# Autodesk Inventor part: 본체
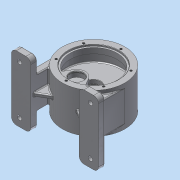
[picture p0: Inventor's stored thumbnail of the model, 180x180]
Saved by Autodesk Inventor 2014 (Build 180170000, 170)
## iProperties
Created: 2025-12
Part Number: 본체
Material: 알루미늄 6061
Document SubType Name: Modeling
Designer: dg
Density: 2.71 g/cm^3
Appearance: 알루미늄 - 평지
Mass: 5646.09 g
Surface Area: 3060.39 cm^2
Volume: 2083.43 cm^3
Author: dg
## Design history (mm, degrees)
sketch "스케치1"
  geometry: C1 r 97 at (0, 0); 1 further point
  constraints: 1 centre point, 1 coincident
  dimensions: "d0" = 194 diameter of C1
extrude "돌출1" new body sketch "스케치1" stored distance "d1" = 124; taper "d2" = 0 deg
sketch "스케치2"
  geometry: L1 (97, 62)-(-97, 62) reference; L2 (-97, -62)-(97, -62) reference; L3 (0, 62)-(0, -62); L4 (0, 62)-(78, 62); L5 (78, 62)-(78, 57); L6 (78, 57)-(73, 57); L7 (73, 57)-(73, 40); L8 (73, 40)-(87, 40); L9 (87, 40)-(87, 8); L10 (87, 8)-(21, 8); L11 (21, 8)-(21, -4); L12 (21, -4)-(19, -4); L13 (19, -4)-(19, -8); L14 (19, -8)-(87, -8); L15 (87, -8)-(87, -40); L16 (87, -40)-(73, -40); L17 (73, -40)-(73, -57); L18 (73, -57)-(78, -57); L19 (78, -57)-(78, -62); L20 (78, -62)-(0, -62); 1 further point
  constraints: 36 end point, 12 parallel, 4 perpendicular, 3 collinear, 3 vertical alignment, 2 midpoint, 2 point on line
  dimensions: "d3" = 156 diameter of L5 L3; "d4" = 146 diameter of L7 L3; "d5" = 174 diameter of L9 L3; "d6" = 5 distance of L4.end L5.end; "d8" = 32 distance of L8.end L9.end; "d9" = 22 distance between parallel lines of L8 L1; "d10" = 66 distance between parallel lines of L12 L1; "d11" = 42 diameter of L11 L3; "d12" = 38 diameter of L13 L3
revolve "회전1" sketch "스케치2" stored, may be unused: angle "d13" = 90 deg
sketch "스케치3"
  geometry: L1 (-23.383, -39)-(-37.148, -62.842); L2 (23.383, -39)-(37.148, -62.842); L3 (0, -52.5)-(0, -73); C1 r 78 at (0, 0) reference; A1 r 73 centre (0, 0) between (-37.148, -62.842) and (37.148, -62.842) reference; A2 r 27 centre (0, -52.5) between (23.383, -39) and (-23.383, -39)
  constraints: 6 end point, 5 point on circle, 2 tangent, 1 centre point, 1 vertical, 1 vertical alignment
  dimensions: "d14" = 52.5 distance of L3.start C1.centre; "d15" = 27 radius of A2; "d16" = 30 deg angle of L3 L2; "d17" = 30 deg angle of L3 L1
extrude "돌출2" join sketch "스케치3" distance "d18" = 17; taper "d19" = 0 deg
sketch "스케치4"
  geometry: L1 (-25.5, 57)-(-39, 57) reference; L2 (-39, 57)-(-62.842, 57) reference; L3 (78, 57)-(-78, 57) reference; L4 (87, -8)-(-87, -8) reference; L5 (-52.5, 57)-(-52.5, -8); L6 (-52.5, -8)-(-33.5, -8); L7 (-33.5, -8)-(-33.5, -4); L8 (-33.5, -4)-(-31.5, -4); L9 (87, 8)-(-87, 8) reference; L10 (-31.5, -4)-(-31.5, 8); L11 (-31.5, 8)-(-52.5, 8); L12 (-78, 62)-(78, 62) reference; L13 (-52.5, 57)-(-31.5, 57); L14 (-31.5, 57)-(-31.5, 53.95); L15 (-31.5, 53.95)-(-30.25, 53.95); L16 (-30.25, 53.95)-(-30.25, 52); L17 (-30.25, 52)-(-31.5, 52); L18 (-39, 40)-(-25.5, 40) reference; L19 (-62.842, 40)-(-39, 40) reference; L20 (-31.5, 52)-(-31.5, 40); L21 (-31.5, 40)-(-52.5, 40); 1 further point
  constraints: 26 end point, 10 point on line, 7 perpendicular, 2 parallel
  dimensions: "d20" = 52.5 distance from line of L5 point (0, 0); "d21" = 38 diameter of L7 L5; "d22" = 42 diameter of L10 L5; "d23" = 66 distance between parallel lines of L8 L12; "d24" = 42 diameter of L14 L5; "d25" = 44.5 diameter of L16 L5; "d26" = 1.95 distance of L15.end L16.end; "d27" = 12 distance of L17.end L20.end; "d28" = 42 diameter of L20 L5
revolve "회전2" sketch "스케치4" stored, may be unused: angle "d29" = 90 deg
sketch "스케치5"
  geometry: C1 r 78 at (0, 0) reference; 1 further point
  constraints: 1 vertical alignment
  dimensions: "d30" = 85 distance of C1.centre point (0, 85)
hole "구멍1" sketch "스케치5" at (0, 85) diameter "d31" = 6.917; stored, may be unused: countersink angle "d35" = 90 deg, drill point angle "d37" = 118 deg; dims "d32" = 16, "d33" = 4, "d34" = 2, "d36" = 18
node "작업 평면1"
sketch "스케치6"
  geometry: L1 (-97, -62)-(-97, 62) reference; L2 (97, -62)-(97, 62) reference; L3 (-75, 100)-(-135, 100); L4 (-135, 100)-(-135, -100); L5 (-135, -100)-(-75, -100); L6 (-75, -100)-(-75, 100); L7 (135, 100)-(75, 100); L8 (75, 100)-(75, -100); L9 (75, -100)-(135, -100); L10 (135, -100)-(135, 100); 3 further points
  constraints: 16 end point, 4 parallel, 2 equal length, 2 horizontal, 2 horizontal alignment, 2 midpoint, 2 perpendicular
  dimensions: "d42" = 150 distance between parallel lines of L8 L6; "d43" = 75 distance from line of point (0, 0) L6; "d44" = 60 distance of L3.start L3.end; "d45" = 200 distance of L3.end L4.end
extrude "돌출3" join sketch "스케치6" distance "d46" = 20; taper "d47" = 0 deg
fillet "모깎기1" dims "d48" = 15
sketch "스케치7"
  geometry: 3 further points
  constraints: 1 vertical alignment
  dimensions: "d49" = 150 distance of point (110, -75) point (110, 75); "d50" = 75 vertical distance of point (0, 0) point (110, 75); "d51" = 110 horizontal distance of point (110, 75) point (0, 0)
hole "구멍2" sketch "스케치7" at (110, -75), (110, 75) diameter "d52" = 13.5; stored, may be unused: countersink angle "d56" = 90 deg, drill point angle "d58" = 118 deg; dims "d53" = 16, "d54" = 33, "d55" = 2, "d57" = 18
sketch "스케치8"
  geometry: L1 (75, 85)-(75, -85) reference; L2 (75, 50)-(97, 50); L3 (97, 50)-(97, -50); L4 (97, -50)-(75, -50); L5 (75, -50)-(75, 50); 2 further points
  constraints: 8 end point, 2 parallel, 1 horizontal, 1 horizontal alignment, 1 midpoint, 1 perpendicular, 1 point on line
  dimensions: "d59" = 22 distance of L2.start L2.end; "d60" = 100 distance of L2.end L3.end
extrude "돌출4" join sketch "스케치8" stored distance "d61" = 20; taper "d62" = 0 deg
sketch "스케치9"
  geometry: L1 (75, -100)-(75, -61.514) reference; L2 (75, -120)-(75, -100) reference; L3 (36.6, -89.83)-(75, -112); A1 r 97 centre (0, 0) between (75, -61.514) and (36.6, -89.83) reference; 1 further point
  constraints: 2 end point, 1 point on circle, 1 point on line
  dimensions: "d63" = 8 distance of L3.end L2.start; "d64" = 60 deg angle of L3 L1
feature "리브1" sketch "스케치9" dims "d65" = 1, "d66" = 12, "d67" = 0, "d68" = 0, "d69" = 1, "d70" = 1
chamfer "모따기1" distance "d75" = 1; stored, may be unused: second distance "d76" = 2, angle "d77" = 45 deg
fillet "모깎기2" dims "d78" = 3
fillet "모깎기3" dims "d79" = 0.6
node "작업 평면3"
fillet "모깎기12" dims "d90" = 3
fillet "모깎기13" dims "d91" = 3
fillet "모깎기14" dims "d92" = 3
fillet "모깎기15" dims "d93" = 3
fillet "모깎기16" dims "d94" = 3
fillet "모깎기17" dims "d95" = 3
fillet "모깎기18" dims "d96" = 3
fillet "모깎기19" dims "d97" = 3
sketch "스케치13"
  geometry: 2 further points
  constraints: 1 coincident, 1 other
feature "엠보싱3" sketch "스케치13" dims "d3" = 156, "d4" = 146, "d5" = 174, "d6" = 5, "d8" = 32, "d9" = 22, "d10" = 66, "d11" = 42, "d12" = 38, "d98" = 0.5, "d99" = 0
fillet "모깎기21" dims "d103" = 3
node "솔리드1"
mirror "대칭1"
pattern_circular "원형 패턴1" dims angle "d39" = 360 deg
mirror "대칭2"
